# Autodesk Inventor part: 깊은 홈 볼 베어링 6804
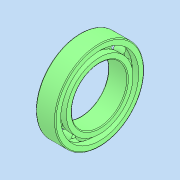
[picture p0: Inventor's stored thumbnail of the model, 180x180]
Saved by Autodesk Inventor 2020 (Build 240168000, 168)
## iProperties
Created: 2025-01
Part Number: 깊은 홈 볼 베어링 6804
Material: 강철, 연강
Description: 깊은 그루부 볼 베어링
Document SubType Name: Modeling
Designer: 1강의실14
Density: 7.85 g/cm^3
Appearance: 기본값
Author: jhkim
Sending System: Autodesk Inventor 2025
Preprocessor: ST-DEVELOPER v20
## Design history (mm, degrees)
feature "Solid1"
feature "Solid1:1"
feature "Solid1:2"
feature "Solid1:3"
feature "Solid1:4"
feature "Solid1:5"
feature "Solid1:6"
feature "Solid1:7"
feature "Solid1:8"
feature "Solid1:9"
feature "Solid1:10"
feature "Solid1:11"
feature "Solid1:12"
feature "Solid1:13"
feature "Solid1:14"
node "솔리드1"
node "솔리드2"
node "솔리드3"
node "솔리드4"
node "솔리드5"
node "솔리드6"
node "솔리드7"
node "솔리드8"
node "솔리드9"
node "솔리드10"
node "솔리드11"
node "솔리드12"
node "솔리드13"
node "솔리드14"
node "솔리드15"
